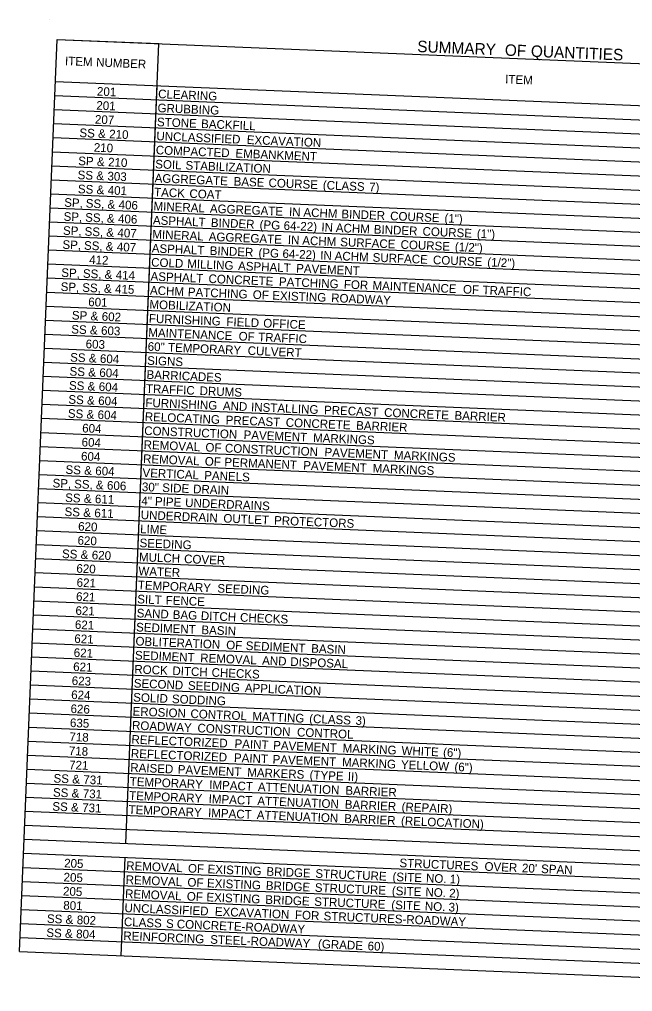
# Model space of a CAD drawing. Extents: x 1164179 to 1171425, y 1655958 to 1657208.
# Drawn here: x 1169924 to 1170350, y 1656114 to 1656789 of the extents above; entities that cross this region are included whole.
import ezdxf

# ---------------------------------------------------------------- set-up
doc = ezdxf.new("R2010")
doc.units = 0
doc.layers.add('Default', color=7, linetype='Continuous')

msp = doc.modelspace()

# ---------------------------------------------------------------- linework, layer by layer
at = {"layer": 'Default'}
for p, q in [((1169945.22, 1656789.02), (1169945.22, 1656789.02)), ((1169924.3, 1656141.93), (1169950.5, 1656775.14)), ((1169924.3, 1656141.93), (1169950.5, 1656775.14)), ((1169950.5, 1656775.14), (1170021.12, 1656772.22)), ((1169950.5, 1656775.14), (1170622.19, 1656747.35)), ((1169998.15, 1656216.94), (1170021.12, 1656772.22)), ((1169949.29, 1656745.91), (1170620.98, 1656718.13)), ((1169998.15, 1656216.94), (1170019.92, 1656742.99)), ((1169948.89, 1656736.17), (1170620.57, 1656708.39)), ((1169948.48, 1656726.43), (1170620.17, 1656698.64)), ((1169948.08, 1656716.69), (1170619.77, 1656688.9)), ((1169947.68, 1656706.95), (1170619.36, 1656679.16)), ((1169947.27, 1656697.21), (1170618.96, 1656669.42)), ((1169946.87, 1656687.46), (1170618.56, 1656659.68)), ((1169946.47, 1656677.72), (1170618.16, 1656649.94)), ((1169946.06, 1656667.98), (1170617.75, 1656640.19)), ((1169945.66, 1656658.24), (1170617.35, 1656630.45)), ((1169945.26, 1656648.5), (1170616.95, 1656620.71)), ((1169944.86, 1656638.76), (1170616.54, 1656610.97)), ((1169944.45, 1656629.01), (1170616.14, 1656601.23)), ((1169944.05, 1656619.27), (1170615.74, 1656591.49)), ((1169943.65, 1656609.53), (1170615.33, 1656581.74)), ((1169943.24, 1656599.79), (1170614.93, 1656572)), ((1169942.84, 1656590.05), (1170614.53, 1656562.26)), ((1169942.44, 1656580.31), (1170614.13, 1656552.52)), ((1169942.03, 1656570.56), (1170613.72, 1656542.78)), ((1169941.63, 1656560.82), (1170613.32, 1656533.04)), ((1169941.23, 1656551.08), (1170612.92, 1656523.29)), ((1169940.83, 1656541.34), (1170612.51, 1656513.55)), ((1169940.42, 1656531.6), (1170612.11, 1656503.81)), ((1169940.02, 1656521.86), (1170611.71, 1656494.07)), ((1169939.62, 1656512.11), (1170611.3, 1656484.33)), ((1169939.21, 1656502.37), (1170610.9, 1656474.59)), ((1169938.81, 1656492.63), (1170610.5, 1656464.84)), ((1169938.41, 1656482.89), (1170610.1, 1656455.1)), ((1169938, 1656473.15), (1170609.69, 1656445.36)), ((1169937.6, 1656463.41), (1170609.29, 1656435.62)), ((1169937.2, 1656453.66), (1170608.89, 1656425.88)), ((1169936.8, 1656443.92), (1170608.48, 1656416.14)), ((1169936.39, 1656434.18), (1170608.08, 1656406.39)), ((1169935.99, 1656424.44), (1170607.68, 1656396.65)), ((1169935.59, 1656414.7), (1170607.27, 1656386.91)), ((1169935.18, 1656404.96), (1170606.87, 1656377.17)), ((1169934.78, 1656395.21), (1170606.47, 1656367.43)), ((1169934.38, 1656385.47), (1170606.07, 1656357.69)), ((1169933.97, 1656375.73), (1170605.66, 1656347.94)), ((1169933.57, 1656365.99), (1170605.26, 1656338.2)), ((1169933.17, 1656356.25), (1170604.86, 1656328.46)), ((1169932.77, 1656346.51), (1170604.45, 1656318.72)), ((1169932.36, 1656336.76), (1170604.05, 1656308.98)), ((1169931.96, 1656327.02), (1170603.65, 1656299.24)), ((1169931.56, 1656317.28), (1170603.24, 1656289.49)), ((1169931.15, 1656307.54), (1170602.84, 1656279.75)), ((1169930.75, 1656297.8), (1170602.44, 1656270.01)), ((1169930.35, 1656288.06), (1170602.04, 1656260.27)), ((1169929.94, 1656278.31), (1170601.63, 1656250.53)), ((1169929.54, 1656268.57), (1170601.23, 1656240.79)), ((1169929.14, 1656258.83), (1170600.83, 1656231.04)), ((1169928.74, 1656249.09), (1170600.42, 1656221.3)), ((1169928.33, 1656239.35), (1170600.02, 1656211.56)), ((1169927.93, 1656229.61), (1170599.62, 1656201.82)), ((1169927.53, 1656219.86), (1170599.21, 1656192.08)), ((1169927.12, 1656210.12), (1170598.81, 1656182.34)), ((1169994.93, 1656139.01), (1169997.75, 1656207.2)), ((1169994.93, 1656139.01), (1169997.75, 1656207.2)), ((1169926.72, 1656200.38), (1170598.41, 1656172.59)), ((1169926.32, 1656190.64), (1170598.01, 1656162.85)), ((1169925.91, 1656180.9), (1170597.6, 1656153.11)), ((1169925.51, 1656171.16), (1170597.2, 1656143.37)), ((1169925.11, 1656161.41), (1170596.8, 1656133.63)), ((1169924.71, 1656151.67), (1170596.39, 1656123.89)), ((1169924.3, 1656141.93), (1170595.99, 1656114.14))]:
    msp.add_line(p, q, dxfattribs=at)

# ---------------------------------------------------------------- texts
for s, height, p in [(' SUMMARY', 8, (1170197.48, 1656766.52)), (' OF', 8, (1170258.31, 1656764.01)), (' QUANTITIES', 8, (1170276.4, 1656763.26)), ('ITEM', 6, (1169955.85, 1656757.28)), (' NUMBER', 6, (1169975.26, 1656756.48)), ('ITEM', 6, (1170261.54, 1656744.63)), ('201', 6, (1169978.03, 1656736.17)), ('CLEARING', 6, (1170020.54, 1656734.41)), ('201', 6, (1169977.63, 1656726.43)), ('GRUBBING', 6, (1170020.13, 1656724.67)), ('207', 6, (1169976.65, 1656716.71)), ('STONE', 6, (1170019.73, 1656714.93)), (' BACKFILL', 6, (1170048.14, 1656713.75)), ('SS', 6, (1169965.86, 1656707.4)), (' &', 6, (1169976.6, 1656706.95)), (' 210', 6, (1169984.32, 1656706.63)), ('UNCLASSIFIED', 6, (1170019.33, 1656705.19)), (' EXCAVATION', 6, (1170079.86, 1656702.68)), ('210', 6, (1169975.85, 1656697.23)), ('COMPACTED', 6, (1170018.92, 1656695.44)), (' EMBANKMENT', 6, (1170072, 1656693.25)), ('SP', 6, (1169965.02, 1656687.91)), (' &', 6, (1169975.83, 1656687.47)), (' 210', 6, (1169983.55, 1656687.15)), ('SOIL', 6, (1170018.52, 1656685.7)), (' STABILIZATION', 6, (1170037.31, 1656684.92)), ('SS', 6, (1169964.64, 1656678.17)), (' &', 6, (1169975.38, 1656677.73)), (' 303', 6, (1169983.1, 1656677.41)), ('AGGREGATE', 6, (1170018.12, 1656675.96)), (' BASE', 6, (1170070.74, 1656673.78)), (' COURSE', 6, (1170094.97, 1656672.78)), (' (CLASS', 6, (1170132.69, 1656671.22)), ('SS', 6, (1169964.82, 1656668.41)), (' &', 6, (1169975.56, 1656667.96)), (' 401', 6, (1169983.28, 1656667.64)), ('TACK', 6, (1170017.72, 1656666.22)), (' COAT', 6, (1170040.04, 1656665.29)), (' 7)', 6, (1170164.83, 1656669.89)), ('SP,', 6, (1169955.29, 1656659.04)), (' SS,', 6, (1169968.04, 1656658.51)), (' &', 6, (1169983.13, 1656657.89)), (' 406', 6, (1169990.85, 1656657.57)), ('MINERAL', 6, (1170017.31, 1656656.48)), (' AGGREGATE', 6, (1170054.25, 1656654.95)), (' IN', 6, (1170109.2, 1656652.68)), (' ACHM', 6, (1170119.21, 1656652.26)), (' BINDER', 6, (1170145.57, 1656651.17)), ('SP,', 6, (1169954.88, 1656649.3)), (' SS,', 6, (1169967.64, 1656648.77)), (' &', 6, (1169982.72, 1656648.15)), (' 406', 6, (1169990.45, 1656647.83)), ('ASPHALT', 6, (1170016.91, 1656646.74)), (' BINDER', 6, (1170054.92, 1656645.16)), (' (PG', 6, (1170088.78, 1656643.76)), (' COURSE', 6, (1170179.43, 1656649.77)), (' (1")', 6, (1170217.15, 1656648.21)), ('SP,', 6, (1169954.48, 1656639.56)), (' SS,', 6, (1169967.24, 1656639.03)), (' &', 6, (1169982.32, 1656638.41)), (' 407', 6, (1169990.04, 1656638.09)), ('MINERAL', 6, (1170016.51, 1656636.99)), (' 64-22)', 6, (1170105.47, 1656643.07)), (' IN', 6, (1170131.69, 1656641.99)), (' ACHM', 6, (1170141.71, 1656641.57)), (' BINDER', 6, (1170168.07, 1656640.48)), (' COURSE', 6, (1170201.93, 1656639.08)), (' (1")', 6, (1170239.65, 1656637.52)), (' AGGREGATE', 6, (1170053.44, 1656635.47)), (' IN', 6, (1170108.39, 1656633.19)), (' ACHM', 6, (1170118.41, 1656632.78)), (' SURFACE', 6, (1170144.77, 1656631.69)), ('SP,', 6, (1169954.08, 1656629.82)), (' SS,', 6, (1169966.83, 1656629.29)), (' &', 6, (1169981.92, 1656628.67)), (' 407', 6, (1169989.64, 1656628.35)), ('ASPHALT', 6, (1170016.1, 1656627.25)), (' BINDER', 6, (1170054.11, 1656625.68)), (' (PG', 6, (1170087.97, 1656624.28)), (' 64-22)', 6, (1170104.66, 1656623.59)), (' COURSE', 6, (1170186.67, 1656629.95)), (' (1/2")', 6, (1170224.39, 1656628.39)), ('412', 6, (1169972.65, 1656619.29)), ('COLD', 6, (1170015.7, 1656617.51)), (' IN', 6, (1170130.89, 1656622.5)), (' ACHM', 6, (1170140.9, 1656622.09)), (' SURFACE', 6, (1170167.26, 1656621)), (' COURSE', 6, (1170209.17, 1656619.26)), (' (1/2")', 6, (1170246.89, 1656617.7)), ('SP,', 6, (1169953.28, 1656610.33)), (' MILLING', 6, (1170038.52, 1656616.57)), (' ASPHALT', 6, (1170073.83, 1656615.11)), (' PAVEMENT', 6, (1170114.16, 1656613.44)), (' SS,', 6, (1169966.04, 1656609.81)), (' &', 6, (1169981.13, 1656609.18)), (' 414', 6, (1169988.85, 1656608.86)), ('ASPHALT', 6, (1170015.3, 1656607.77)), (' CONCRETE', 6, (1170053.3, 1656606.2)), (' PATCHING', 6, (1170102.19, 1656604.17)), ('SP,', 6, (1169952.85, 1656600.59)), (' SS,', 6, (1169965.6, 1656600.07)), (' &', 6, (1169980.69, 1656599.44)), (' 415', 6, (1169988.41, 1656599.12)), ('ACHM', 6, (1170014.89, 1656598.03)), (' PATCHING', 6, (1170038.93, 1656597.03)), (' FOR', 6, (1170147.28, 1656602.31)), (' MAINTENANCE', 6, (1170167.17, 1656601.49)), (' OF', 6, (1170230.02, 1656598.89)), (' TRAFFIC', 6, (1170243.6, 1656598.32)), ('601', 6, (1169971.99, 1656590.04)), (' OF', 6, (1170084.01, 1656595.17)), (' EXISTING', 6, (1170097.59, 1656594.61)), (' ROADWAY', 6, (1170138.49, 1656592.91)), ('MOBILIZATION', 6, (1170014.49, 1656588.29)), ('SP', 6, (1169960.61, 1656580.76)), (' &', 6, (1169971.42, 1656580.31)), (' 602', 6, (1169979.14, 1656579.99)), ('FURNISHING', 6, (1170014.09, 1656578.54)), (' FIELD', 6, (1170065.68, 1656576.41)), ('SS', 6, (1169960.21, 1656571.01)), (' &', 6, (1169970.95, 1656570.57)), (' 603', 6, (1169978.67, 1656570.25)), (' OFFICE', 6, (1170091.3, 1656575.35)), ('MAINTENANCE', 6, (1170013.69, 1656568.8)), (' OF', 6, (1170074.21, 1656566.3)), (' TRAFFIC', 6, (1170087.79, 1656565.74)), ('603', 6, (1169970.2, 1656560.84)), ('60"', 6, (1170013.28, 1656559.06)), (' TEMPORARY', 6, (1170025.18, 1656558.57)), (' CULVERT', 6, (1170080.5, 1656556.28)), ('SS', 6, (1169959.42, 1656551.53)), (' &', 6, (1169970.16, 1656551.09)), (' 604', 6, (1169977.88, 1656550.77)), ('SIGNS', 6, (1170012.88, 1656549.32)), ('SS', 6, (1169959.02, 1656541.79)), (' &', 6, (1169969.75, 1656541.34)), (' 604', 6, (1169977.48, 1656541.02)), ('BARRICADES', 6, (1170012.48, 1656539.58)), ('SS', 6, (1169958.61, 1656532.05)), (' &', 6, (1169969.35, 1656531.6)), (' 604', 6, (1169977.07, 1656531.28)), ('TRAFFIC', 6, (1170012.07, 1656529.84)), ('SS', 6, (1169958.21, 1656522.3)), (' DRUMS', 6, (1170047.11, 1656528.39)), (' &', 6, (1169968.95, 1656521.86)), (' 604', 6, (1169976.67, 1656521.54)), ('FURNISHING', 6, (1170011.67, 1656520.09)), (' AND', 6, (1170063.27, 1656517.96)), (' INSTALLING', 6, (1170082.83, 1656517.15)), ('SS', 6, (1169957.81, 1656512.56)), (' &', 6, (1169968.54, 1656512.12)), (' 604', 6, (1169976.27, 1656511.8)), ('RELOCATING', 6, (1170011.27, 1656510.35)), (' PRECAST', 6, (1170133.51, 1656515.05)), (' CONCRETE', 6, (1170175.23, 1656513.33)), (' BARRIER', 6, (1170224.12, 1656511.3)), ('604', 6, (1169967.8, 1656502.39)), (' PRECAST', 6, (1170065.2, 1656508.12)), (' CONCRETE', 6, (1170106.93, 1656506.39)), (' BARRIER', 6, (1170155.81, 1656504.37)), ('CONSTRUCTION', 6, (1170010.86, 1656500.61)), (' PAVEMENT', 6, (1170077.66, 1656497.85)), (' MARKINGS', 6, (1170125.9, 1656495.85)), ('604', 6, (1169967.39, 1656492.65)), ('REMOVAL', 6, (1170010.46, 1656490.87)), (' OF', 6, (1170051.13, 1656489.19)), (' CONSTRUCTION', 6, (1170064.7, 1656488.62)), ('604', 6, (1169966.99, 1656482.91)), (' PAVEMENT', 6, (1170133.82, 1656485.77)), (' MARKINGS', 6, (1170182.06, 1656483.77)), ('REMOVAL', 6, (1170010.06, 1656481.13)), (' OF', 6, (1170050.72, 1656479.44)), (' PERMANENT', 6, (1170064.3, 1656478.88)), (' PAVEMENT', 6, (1170119.05, 1656476.62)), ('SS', 6, (1169956.19, 1656473.6)), (' &', 6, (1169966.93, 1656473.15)), (' 604', 6, (1169974.65, 1656472.83)), ('VERTICAL', 6, (1170009.66, 1656471.39)), (' PANELS', 6, (1170050.32, 1656469.7)), (' MARKINGS', 6, (1170167.3, 1656474.62)), ('SP,', 6, (1169947.23, 1656464.21)), (' SS,', 6, (1169959.98, 1656463.68)), (' &', 6, (1169975.07, 1656463.06)), (' 606', 6, (1169982.79, 1656462.74)), ('30"', 6, (1170009.25, 1656461.64)), (' SIDE', 6, (1170021.15, 1656461.15)), (' DRAIN', 6, (1170042.58, 1656460.26)), ('SS', 6, (1169955.95, 1656454.09)), (' &', 6, (1169966.69, 1656453.65)), (' 611', 6, (1169974.41, 1656453.33)), ('4"', 6, (1170008.85, 1656451.9)), (' PIPE', 6, (1170016.09, 1656451.6)), (' UNDERDRAINS', 6, (1170037.06, 1656450.73)), ('SS', 6, (1169955.55, 1656444.35)), (' &', 6, (1169966.29, 1656443.9)), (' 611', 6, (1169974.01, 1656443.58)), ('UNDERDRAIN', 6, (1170008.45, 1656442.16)), (' OUTLET', 6, (1170063.61, 1656439.88)), (' PROTECTORS', 6, (1170098.81, 1656438.42)), ('620', 6, (1169964.97, 1656434.2)), ('LIME', 6, (1170008.04, 1656432.42)), ('620', 6, (1169964.57, 1656424.46)), ('SEEDING', 6, (1170007.64, 1656422.68)), ('SS', 6, (1169953.77, 1656415.15)), (' &', 6, (1169964.51, 1656414.7)), (' 620', 6, (1169972.23, 1656414.38)), ('MULCH', 6, (1170007.24, 1656412.94)), (' COVER', 6, (1170036.34, 1656411.73)), ('620', 6, (1169963.76, 1656404.98)), ('WATER', 6, (1170006.83, 1656403.19)), ('621', 6, (1169963.93, 1656395.21)), ('TEMPORARY', 6, (1170006.43, 1656393.45)), (' SEEDING', 6, (1170059.43, 1656391.26)), ('621', 6, (1169963.53, 1656385.47)), ('SILT', 6, (1170006.03, 1656383.71)), (' FENCE', 6, (1170023.55, 1656382.99)), ('621', 6, (1169963.12, 1656375.73)), ('SAND', 6, (1170005.63, 1656373.97)), (' BAG', 6, (1170028.45, 1656373.02)), (' DITCH', 6, (1170047.95, 1656372.22)), (' CHECKS', 6, (1170075.19, 1656371.09)), ('621', 6, (1169962.72, 1656365.98)), ('SEDIMENT', 6, (1170005.22, 1656364.23)), (' BASIN', 6, (1170048.34, 1656362.44)), ('621', 6, (1169962.32, 1656356.24)), ('OBLITERATION', 6, (1170004.82, 1656354.49)), (' OF', 6, (1170065.57, 1656351.97)), (' SEDIMENT', 6, (1170079.15, 1656351.41)), (' BASIN', 6, (1170124.59, 1656349.53)), ('621', 6, (1169961.91, 1656346.5)), ('SEDIMENT', 6, (1170004.42, 1656344.74)), (' REMOVAL', 6, (1170047.53, 1656342.96)), (' AND', 6, (1170090.52, 1656341.18)), (' DISPOSAL', 6, (1170110.09, 1656340.37)), ('621', 6, (1169961.51, 1656336.76)), ('ROCK', 6, (1170004.01, 1656335)), (' DITCH', 6, (1170028.2, 1656334)), ('623', 6, (1169960.53, 1656327.04)), (' CHECKS', 6, (1170055.44, 1656332.87)), ('SECOND', 6, (1170003.61, 1656325.26)), (' SEEDING', 6, (1170039, 1656323.8)), (' APPLICATION', 6, (1170078.51, 1656322.16)), ('624', 6, (1169960.14, 1656317.3)), ('SOLID', 6, (1170003.21, 1656315.52)), (' SODDING', 6, (1170027.9, 1656314.5)), ('626', 6, (1169959.72, 1656307.56)), ('EROSION', 6, (1170002.8, 1656305.78)), (' CONTROL', 6, (1170040.75, 1656304.21)), (' MATTING', 6, (1170083.74, 1656302.43)), (' (CLASS', 6, (1170123.23, 1656300.8)), (' 3)', 6, (1170155.37, 1656299.47)), ('635', 6, (1169959.3, 1656297.82)), ('ROADWAY', 6, (1170002.4, 1656296.04)), (' CONSTRUCTION', 6, (1170045.62, 1656294.25)), ('718', 6, (1169958.91, 1656288.08)), ('REFLECTORIZED', 6, (1170002, 1656286.29)), (' CONTROL', 6, (1170114.74, 1656291.39)), (' PAINT', 6, (1170071.36, 1656283.42)), (' PAVEMENT', 6, (1170098.19, 1656282.31)), (' MARKING', 6, (1170146.43, 1656280.32)), ('718', 6, (1169958.51, 1656278.33)), ('REFLECTORIZED', 6, (1170001.6, 1656276.55)), (' PAINT', 6, (1170070.96, 1656273.68)), (' WHITE', 6, (1170187.33, 1656278.63)), (' (6")', 6, (1170216.19, 1656277.43)), ('721', 6, (1169958.69, 1656268.57)), ('RAISED', 6, (1170001.19, 1656266.81)), (' PAVEMENT', 6, (1170097.79, 1656272.57)), (' MARKING', 6, (1170146.03, 1656270.58)), (' YELLOW', 6, (1170186.92, 1656268.88)), (' (6")', 6, (1170224.06, 1656267.35)), ('SS', 6, (1169947.89, 1656259.26)), (' PAVEMENT', 6, (1170031.93, 1656265.54)), (' MARKERS', 6, (1170080.18, 1656263.54)), (' (TYPE', 6, (1170123.49, 1656261.75)), (' II)', 6, (1170150.04, 1656260.65)), (' &', 6, (1169958.63, 1656258.81)), (' 731', 6, (1169966.35, 1656258.49)), ('TEMPORARY', 6, (1170000.79, 1656257.07)), (' IMPACT', 6, (1170053.79, 1656254.88)), (' ATTENUATION', 6, (1170087.59, 1656253.48)), ('SS', 6, (1169947.49, 1656249.51)), (' &', 6, (1169958.23, 1656249.07)), (' 731', 6, (1169965.95, 1656248.75)), ('TEMPORARY', 6, (1170000.39, 1656247.33)), (' BARRIER', 6, (1170148.34, 1656250.96)), ('SS', 6, (1169947.09, 1656239.77)), (' &', 6, (1169957.83, 1656239.33)), (' 731', 6, (1169965.55, 1656239.01)), (' IMPACT', 6, (1170053.39, 1656245.13)), (' ATTENUATION', 6, (1170087.19, 1656243.74)), (' BARRIER', 6, (1170147.94, 1656241.22)), (' (REPAIR)', 6, (1170187.39, 1656239.59)), ('TEMPORARY', 6, (1169999.98, 1656237.59)), (' IMPACT', 6, (1170052.98, 1656235.39)), (' ATTENUATION', 6, (1170086.79, 1656233.99)), (' BARRIER', 6, (1170147.53, 1656231.48)), (' (RELOCATION)', 6, (1170186.99, 1656229.85)), ('205', 6, (1169955.27, 1656200.4)), ('REMOVAL', 6, (1169998.37, 1656198.62)), ('STRUCTURES', 6, (1170188.12, 1656200.53)), (' OF', 6, (1170039.04, 1656196.94)), (' EXISTING', 6, (1170052.61, 1656196.37)), (' BRIDGE', 6, (1170093.51, 1656194.68)), (' STRUCTURE', 6, (1170127.51, 1656193.28)), (' OVER', 6, (1170244.96, 1656198.18)), (" 20'", 6, (1170270.98, 1656197.1)), (' SPAN', 6, (1170284.25, 1656196.55)), ('205', 6, (1169954.86, 1656190.66)), ('REMOVAL', 6, (1169997.97, 1656188.88)), (' OF', 6, (1170038.64, 1656187.19)), (' EXISTING', 6, (1170052.21, 1656186.63)), (' BRIDGE', 6, (1170093.11, 1656184.94)), (' (SITE', 6, (1170181.05, 1656191.06)), (' NO.', 6, (1170204.33, 1656190.1)), (' 1)', 6, (1170220.82, 1656189.42)), ('205', 6, (1169954.46, 1656180.92)), ('REMOVAL', 6, (1169997.57, 1656179.14)), (' STRUCTURE', 6, (1170127.11, 1656183.53)), (' (SITE', 6, (1170180.64, 1656181.32)), (' NO.', 6, (1170203.93, 1656180.36)), (' 2)', 6, (1170220.41, 1656179.67)), (' OF', 6, (1170038.23, 1656177.45)), (' EXISTING', 6, (1170051.81, 1656176.89)), (' BRIDGE', 6, (1170092.71, 1656175.2)), (' STRUCTURE', 6, (1170126.7, 1656173.79)), (' (SITE', 6, (1170180.24, 1656171.58)), ('801', 6, (1169954.66, 1656171.15)), ('UNCLASSIFIED', 6, (1169997.16, 1656169.39)), (' EXCAVATION', 6, (1170057.69, 1656166.89)), (' NO.', 6, (1170203.53, 1656170.61)), (' 3)', 6, (1170220.01, 1656169.93)), ('SS', 6, (1169943.32, 1656161.86)), (' &', 6, (1169954.05, 1656161.42)), (' 802', 6, (1169961.78, 1656161.1)), ('CLASS', 6, (1169996.76, 1656159.65)), (' S', 6, (1170023.79, 1656158.53)), (' CONCRETE-ROADWAY', 6, (1170031.27, 1656158.22)), (' FOR', 6, (1170113.33, 1656164.59)), (' STRUCTURES-ROADWAY', 6, (1170133.23, 1656163.76)), ('SS', 6, (1169942.9, 1656152.12)), (' &', 6, (1169953.63, 1656151.68)), (' 804', 6, (1169961.36, 1656151.36)), ('REINFORCING', 6, (1169996.36, 1656149.91)), (' STEEL-ROADWAY', 6, (1170054.47, 1656147.51)), (' (GRADE', 6, (1170129.34, 1656144.41)), (' 60)', 6, (1170163.8, 1656142.98))]:
    msp.add_text(s, height=height, rotation=357.63112, dxfattribs=at).set_placement(p)

doc.saveas('drawing.dxf')
